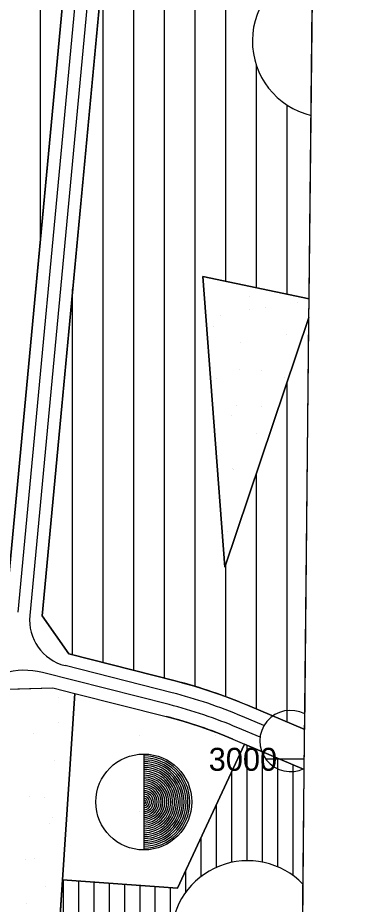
# Model space of a CAD drawing. Extents: x 419109 to 421295, y 4452223 to 4457798.
# Drawn here: x 421152 to 421266.4, y 4452952.7 to 4453242.2 of the extents above; entities that cross this region are included whole.
import ezdxf

# ---------------------------------------------------------------- set-up
doc = ezdxf.new("R2010")
doc.units = 0
for name, color, linetype in [('ADA', 7, 'Continuous'), ('ADAKENARI', 7, 'Continuous'), ('Default', 7, 'Continuous'), ('KALDIRIM', 7, 'Continuous'), ('KD_DAIRE', 7, 'Continuous'), ('LJ_SEMBOL', 7, 'Continuous'), ('PAFTALAMA', 7, 'Continuous'), ('PL_AYA_PARK_DINLENME', 7, 'Continuous'), ('PL_K_YONETIM', 7, 'Continuous'), ('PL_KON_MEV_350', 7, 'Continuous'), ('PL_KON_MEV_450', 7, 'Continuous'), ('SM_DAIRE', 7, 'Continuous'), ('TR_ORTAYOGUNKONUT', 7, 'Continuous'), ('TR_PARKALANI', 7, 'Continuous'), ('TR_YONETIMMERK', 7, 'Continuous'), ('TR_YUKSEKYOGUNKONUT', 7, 'Continuous')]:
    doc.layers.add(name, color=color, linetype=linetype)

# ---------------------------------------------------------------- blocks, each defined once
blk = doc.blocks.new('POINT_DISPLAY')
at = {"layer": 'Default'}
blk.add_line((0, 0), (0, 0), dxfattribs=at)

msp = doc.modelspace()

# ---------------------------------------------------------------- linework, layer by layer
at = {"layer": 'ADA'}
for p, q in [((421247.13, 4453150.36), (421212.38, 4453157.68)), ((421212.38, 4453157.68), (421219.61, 4453062.77)), ((421219.61, 4453062.77), (421247.07, 4453144.24)), ((421166.65, 4452960.6), (421170.69, 4453021.54)), ((421204.14, 4452957.89), (421226.07, 4453004.99)), ((421161.92, 4452889.08), (421166.65, 4452960.6)), ((421166.65, 4452960.6), (421204.14, 4452957.89))]:
    msp.add_line(p, q, dxfattribs=at)
at = {"layer": 'ADAKENARI'}
for p, q in [((421175.98, 4453346.49), (421148.76, 4453056.16)), ((421159.94, 4453046.85), (421187.93, 4453345.37)), ((421168.7, 4453034.43), (421159.94, 4453046.85)), ((421203.41, 4453025.6), (421168.7, 4453034.43)), ((421144.3, 4453022.8), (421163.52, 4453023.36)), ((421163.52, 4453023.36), (421170.69, 4453021.54)), ((421170.69, 4453021.54), (421200.45, 4453013.97)), ((421245.67, 4453009.69), (421226.95, 4453017.65)), ((421222.25, 4453006.61), (421226.07, 4453004.99)), ((421226.07, 4453004.99), (421245.53, 4452996.7))]:
    msp.add_line(p, q, dxfattribs=at)
for radius in [162, 150]:
    msp.add_arc((421163.5, 4452868.6), radius, 66.9411, 75.7392, dxfattribs=at)
at = {"layer": 'KALDIRIM'}
for p, q in [((421173.41, 4453276.24), (421152.02, 4453048.1)), ((421177.43, 4453276.24), (421155.93, 4453046.96)), ((421202.42, 4453021.73), (421167.46, 4453030.61)), ((421201.44, 4453017.85), (421160.09, 4453028.36)), ((421232.38, 4453011), (421225.39, 4453013.97)), ((421231.1, 4453007.19), (421223.82, 4453010.29))]:
    msp.add_line(p, q, dxfattribs=at)
for centre, radius, start, end in [((421171.25, 4453045.52), 15.39, 174.6441, 255.7392), ((421154.41, 4453006.03), 23.04, 75.7392, 107.6274), ((421163.5, 4452868.6), 158, 66.9411, 75.7392), ((421163.5, 4452868.6), 154, 66.9411, 75.7392)]:
    msp.add_arc(centre, radius, start, end, dxfattribs=at)
at = {"layer": 'KD_DAIRE'}
msp.add_line((421245.54, 4452997.05), (421245.72, 4453014.81), dxfattribs=at)
msp.add_arc((421241.03, 4453005.97), 10, 62.0201, 296.7855, dxfattribs=at)
at = {"layer": 'LJ_SEMBOL'}
msp.add_line((421193.16, 4453001.72), (421193.16, 4452970.39), dxfattribs=at)
msp.add_circle((421193.16, 4452986.06), 15.66, dxfattribs=at)
for radius in [15.04, 14.41, 13.78, 13.16, 12.53, 11.9, 11.28, 10.65, 10.02, 9.4, 8.77, 8.14, 7.52, 6.89, 6.26, 5.64, 5.01, 4.39, 3.76, 3.13, 2.51, 1.88, 1.25, 0.627]:
    msp.add_arc((421193.16, 4452986.06), radius, 270, 90, dxfattribs=at)
at = {"layer": 'PAFTALAMA'}
for q in [(421233.07, 4453000), (421245.57, 4453000)]:
    msp.add_line((421245.57, 4453000), q, dxfattribs=at)
msp.add_lwpolyline([(419138.44, 4455021.89), (419108.72, 4452245.78), (421237.47, 4452223.29), (421266.41, 4454999.4)], dxfattribs=at)
at = {"layer": 'PL_AYA_PARK_DINLENME'}
msp.add_line((421247.07, 4453144.24), (421247.13, 4453150.36), dxfattribs=at)
msp.add_lwpolyline([(421247.13, 4453150.36), (421212.38, 4453157.68), (421219.61, 4453062.77), (421247.07, 4453144.24)], dxfattribs=at)
msp.add_lwpolyline([(421166.65, 4452960.6), (421161.92, 4452889.08), (421136.89, 4452888.88), (421144.89, 4452991.74), (421139.68, 4453002.38), (421119.28, 4452995.43), (421112.39, 4453012.66), (421144.3, 4453022.8), (421163.52, 4453023.36), (421170.69, 4453021.54)], close=True, dxfattribs=at)
at = {"layer": 'PL_K_YONETIM'}
msp.add_lwpolyline([(421226.07, 4453004.99), (421204.14, 4452957.89), (421166.65, 4452960.6), (421170.69, 4453021.54), (421200.45, 4453013.97), (421203.24, 4453013.24), (421206, 4453012.45), (421208.76, 4453011.61), (421211.49, 4453010.71), (421214.21, 4453009.76), (421216.91, 4453008.76), (421219.59, 4453007.71), (421222.25, 4453006.61)], close=True, dxfattribs=at)
at = {"layer": 'PL_KON_MEV_350'}
for p, q in [((421247.13, 4453150.36), (421248.9, 4453319.61)), ((421245.67, 4453009.69), (421247.07, 4453144.24))]:
    msp.add_line(p, q, dxfattribs=at)
for points in [[(421103.84, 4453266.28), (421097.65, 4453188.75), (421128.13, 4453187.66), (421125.41, 4453151.19), (421110.71, 4453153.91), (421108.54, 4453121.8), (421133.03, 4453054.85), (421148.76, 4453056.16), (421175.98, 4453346.49)], [(421187.93, 4453345.37), (421159.94, 4453046.85), (421168.7, 4453034.43), (421203.41, 4453025.6), (421206.41, 4453024.81), (421209.41, 4453023.96), (421212.38, 4453023.05), (421215.33, 4453022.08), (421218.27, 4453021.06), (421221.19, 4453019.98), (421224.08, 4453018.84), (421226.95, 4453017.65), (421245.67, 4453009.69)], [(421247.07, 4453144.24), (421219.61, 4453062.77), (421212.38, 4453157.68), (421247.13, 4453150.36)]]:
    msp.add_lwpolyline(points, dxfattribs=at)
at = {"layer": 'PL_KON_MEV_450'}
msp.add_line((421244.42, 4452889.74), (421245.53, 4452996.7), dxfattribs=at)
msp.add_lwpolyline([(421245.53, 4452996.7), (421226.07, 4453004.99), (421204.14, 4452957.89), (421166.65, 4452960.6), (421161.92, 4452889.08), (421244.42, 4452889.74)], dxfattribs=at)
at = {"layer": 'SM_DAIRE'}
for p, q in [((421247.76, 4453210.27), (421248.27, 4453259.01)), ((421244.78, 4452924.23), (421245.14, 4452959.17))]:
    msp.add_line(p, q, dxfattribs=at)
for centre, start, end in [((421253.59, 4453234.59), 102.2885, 256.517), ((421227.08, 4452941.88), 43.7358, 315.0697)]:
    msp.add_arc(centre, 25, start, end, dxfattribs=at)
at = {"layer": 'TR_ORTAYOGUNKONUT'}
for p, q in [((421159.43, 4453169.97), (421159.43, 4453359.35)), ((421189.94, 4453029.03), (421189.94, 4453357.06)), ((421199.94, 4453026.49), (421199.94, 4453355.61)), ((421209.94, 4453023.79), (421209.94, 4453354.16)), ((421219.94, 4453156.09), (421219.94, 4453352.72)), ((421179.94, 4453031.57), (421179.94, 4453260.18)), ((421229.94, 4453153.98), (421229.94, 4453226.47)), ((421239.94, 4453151.88), (421239.94, 4453213.64)), ((421169.94, 4453034.11), (421169.94, 4453153.51)), ((421239.94, 4453012.12), (421239.94, 4453123.09)), ((421229.94, 4453016.38), (421229.94, 4453093.42)), ((421219.94, 4453020.44), (421219.94, 4453063.74))]:
    msp.add_line(p, q, dxfattribs=at)
at = {"layer": 'TR_YUKSEKYOGUNKONUT'}
for p, q in [((421226.92, 4452966.88), (421226.92, 4453004.63)), ((421231.92, 4452966.41), (421231.92, 4453002.5)), ((421236.92, 4452964.87), (421236.92, 4453000.37)), ((421221.92, 4452966.35), (421221.92, 4452996.07)), ((421241.92, 4452962), (421241.92, 4452998.24)), ((421216.92, 4452964.73), (421216.92, 4452985.33)), ((421211.92, 4452961.76), (421211.92, 4452974.6)), ((421206.92, 4452956.67), (421206.92, 4452963.86)), ((421166.92, 4452889.12), (421166.92, 4452960.58)), ((421171.92, 4452889.16), (421171.92, 4452960.22)), ((421176.92, 4452889.2), (421176.92, 4452959.85)), ((421181.92, 4452889.24), (421181.92, 4452959.49)), ((421186.92, 4452889.28), (421186.92, 4452959.13)), ((421191.92, 4452889.32), (421191.92, 4452958.77)), ((421196.92, 4452889.36), (421196.92, 4452958.41)), ((421201.92, 4452889.4), (421201.92, 4452958.05))]:
    msp.add_line(p, q, dxfattribs=at)

# ---------------------------------------------------------------- block references
at = {"layer": 'TR_PARKALANI', "xscale": 0.1, "yscale": 0.10000000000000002}
for p in [(421213.03, 4453149.46), (421227.52, 4453151), (421243.44, 4453149.18), (421227.8, 4453146.86), (421232.96, 4453147.63), (421218.19, 4453145.03), (421216.02, 4453141.36), (421239.62, 4453138.65), (421224.85, 4453136.05), (421224.33, 4453127.16), (421231.51, 4453127.07), (421216.74, 4453124.46), (421239.1, 4453124.56), (421238.17, 4453118.09), (421223.4, 4453115.48), (421231.48, 4453115.16), (421221.73, 4453112.39), (421230.06, 4453106.5), (421221.95, 4453094.92), (421222.58, 4453094.64), (421220.5, 4453074.35), (421165.41, 4453020.08), (421165.16, 4453012.08), (421157.3, 4453008.5), (421163.96, 4452999.52), (421155.85, 4452987.93), (421160.82, 4452987.46), (421162.51, 4452978.96), (421163.35, 4452981.07), (421154.4, 4452967.37), (421157.35, 4452967.76), (421161.06, 4452958.39), (421154.75, 4452952.99)]:
    msp.add_blockref('POINT_DISPLAY', p, dxfattribs=at)
at = {"layer": 'TR_YONETIMMERK', "xscale": 0.1, "yscale": 0.10000000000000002}
for p in [(421191.65, 4453007.89), (421216.65, 4453007.89), (421191.65, 4452982.89)]:
    msp.add_blockref('POINT_DISPLAY', p, dxfattribs=at)

# ---------------------------------------------------------------- texts
at = {"layer": 'PAFTALAMA'}
msp.add_text('3000', height=7.5, dxfattribs=at).set_placement((421214.35, 4452996.25))

doc.saveas('drawing.dxf')
